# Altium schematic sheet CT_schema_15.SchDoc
size 391 x 278 mm
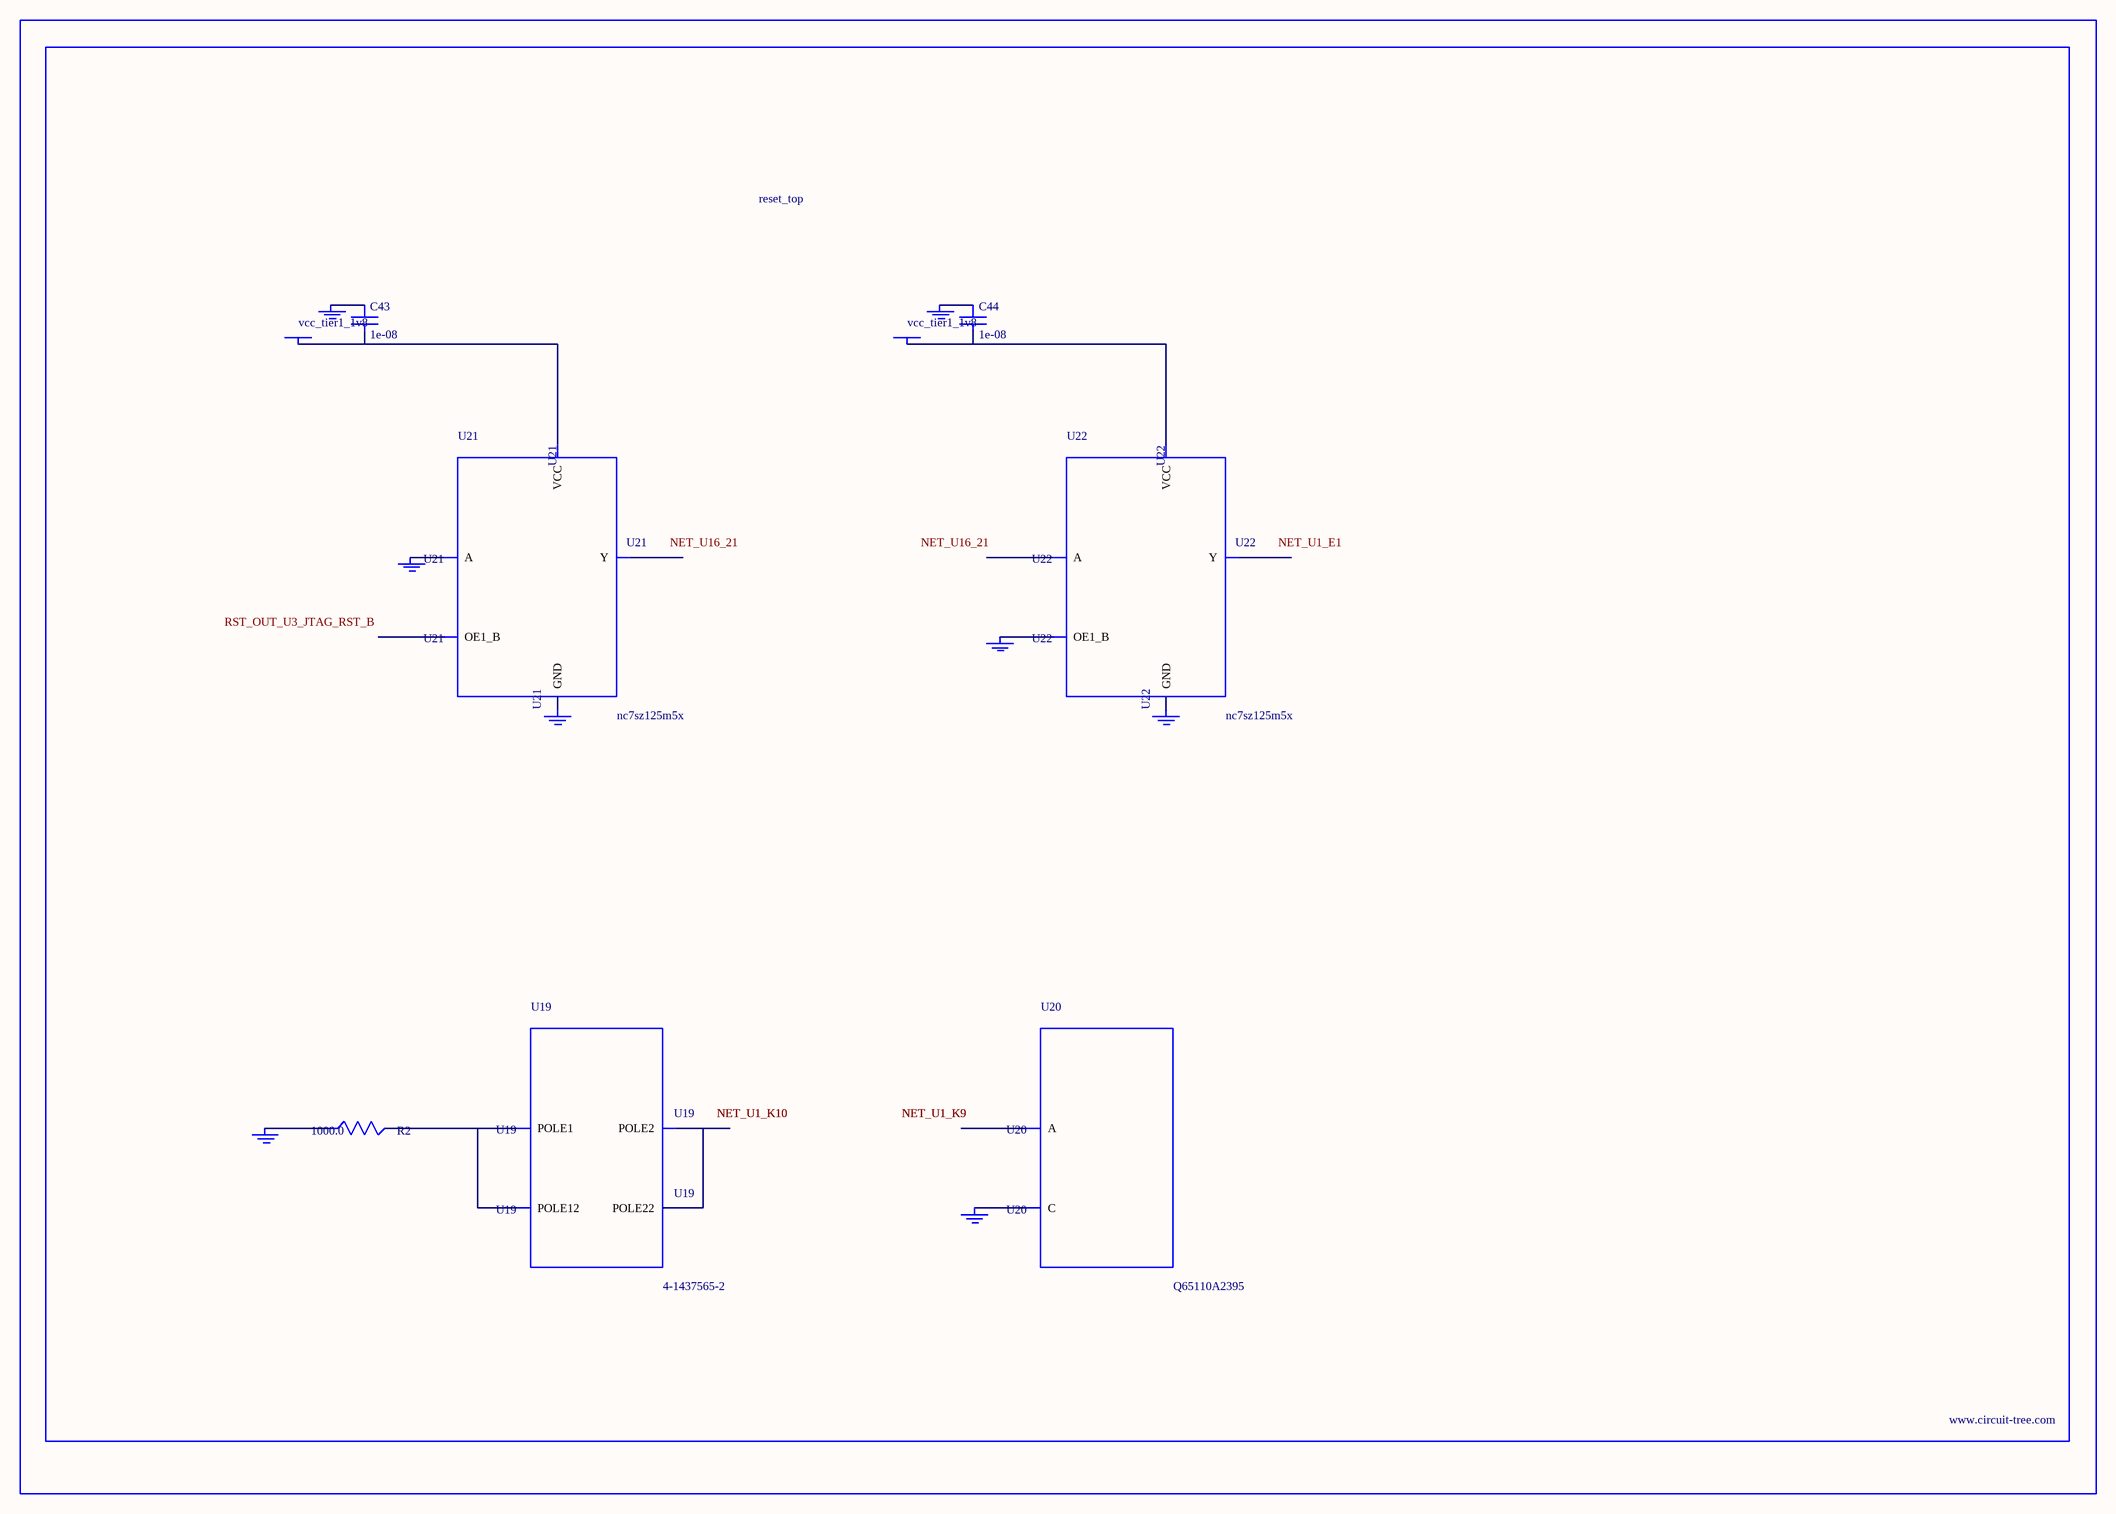
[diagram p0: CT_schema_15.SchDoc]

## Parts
BORDER14  (no value)
C43  1e-08  [C0402]
C44  1e-08  [C0402]
GND_INSTANCE_14_0  (no value)
GND_INSTANCE_14_1  (no value)
GND_INSTANCE_14_2  (no value)
GND_INSTANCE_14_3  (no value)
GND_INSTANCE_14_4  (no value)
GND_INSTANCE_14_5  (no value)
GND_INSTANCE_14_6  (no value)
GND_INSTANCE_14_7  (no value)
POWER_INSTANCE_14_0  vcc_tier1_1v8
POWER_INSTANCE_14_1  vcc_tier1_1v8
R2  1000.0  [R0603]
U19  4-1437565-2  [SW_4-1437565-2]
U20  Q65110A2395  [LGM67K-G1J2-24-Z]
U21  nc7sz125m5x  [NC7SZ125M5X]
U22  nc7sz125m5x  [NC7SZ125M5X]

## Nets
NetC43_1: C43.1 GND_INSTANCE_14_2.0(GND)
NetC43_2: C43.2 POWER_INSTANCE_14_0.0(PWR) U21.5(VCC)
NetC44_1: C44.1 GND_INSTANCE_14_5.0(GND)
NetC44_2: C44.2 POWER_INSTANCE_14_1.0(PWR) U22.5(VCC)
NetGND_INSTANCE_14_0_0: GND_INSTANCE_14_0.0(GND) R2.1
NetGND_INSTANCE_14_1_0: GND_INSTANCE_14_1.0(GND) U20.C
NetGND_INSTANCE_14_3_0: GND_INSTANCE_14_3.0(GND) U21.2(A)
NetGND_INSTANCE_14_4_0: GND_INSTANCE_14_4.0(GND) U21.3(GND)
NetGND_INSTANCE_14_6_0: GND_INSTANCE_14_6.0(GND) U22.1(OE1_B)
NetGND_INSTANCE_14_7_0: GND_INSTANCE_14_7.0(GND) U22.3(GND)
NetR2_2: R2.2 U19.1(POLE1) U19.2(POLE12)
NetU19_3: U19.3(POLE2) U19.4(POLE22)

Not connected (* = marked no-connect by the designer): U20 A; U21 1(OE1_B) 4(Y); U22 2(A) 4(Y)

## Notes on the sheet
- Labels drawn without touching a wire or pin: NET_U1_E1, NET_U16_21, RST_OUT_U3_JTAG_RST_B

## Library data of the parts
BORDER14 = BORDER_PAGE14
C43 C44 = C0402C103K3RAC
GND_INSTANCE_14_0-GND_INSTANCE_14_7 = GND
POWER_INSTANCE_14_0 POWER_INSTANCE_14_1 = PWR
R2 = RC0603JR-071KL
